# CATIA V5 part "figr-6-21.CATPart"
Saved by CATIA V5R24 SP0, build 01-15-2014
Part number: Part1
Bounding box of the stored display mesh (mm): x 0 to 150, y -70 to 70, z -150 to 69.804
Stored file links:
  D:\KAVITA\CATIA V5-6R2014 Project_ Kavita\CATIA V5-6R2014_partfiles\Partfiles\c06_catia_v5-6r2014_prt\figr-6-21.CATPart
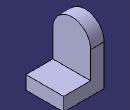
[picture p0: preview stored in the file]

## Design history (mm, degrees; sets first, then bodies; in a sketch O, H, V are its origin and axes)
Body1 (main body)
  Sketch1 on yz-plane, origin (0, 0, 0), H (0, 1, 0), V (0, 0, 1)
    arc A1 centre (0, 0) radius 70 from (70, 0) to (-70, 0) ccw
    point P1 (70, 0)
    point P2 (-70, 0)
    line L1 (-70, 0) -> (-70, -150)
    line L2 (-70, -150) -> (70, -150)
    line L3 (70, -150) -> (70, 0)
    construction circle A2 centre (0, 0) radius 37.5
    radius A1 = 70
    radius A2 = 37.5
    distance O L2 = 150
    coincidence: P1 H, P2 H
    tangency: L1 A1, L3 A1
    horizontal: L2 H
  Pad1: profile Sketch1, direction (1, 0, 0), length 50
  Sketch2 on face of Pad1, origin (50, 0, 0), H (0, 1, 0), V (0, 0, 1)
    line L1 (-70, -150) -> (70, -150)
    line L2 (70, -150) -> (70, -100)
    line L3 (70, -100) -> (-70, -100)
    line L4 (-70, -100) -> (-70, -150)
    reference projected line E1 (-70, -150) -> (70, -150) from edge [face of Pad1 | face of Pad1]
    reference projected line E2 (-70, 0) -> (-70, -150) from edge [face of Pad1 | face of Pad1]
    reference projected line E3 (70, -150) -> (70, 0) from edge [face of Pad1 | face of Pad1]
    length L2 = 50
    horizontal: L1 H, L3 H
    vertical: L2 V, L4 V
    coincidence: L1 E1, E2 L4, L2 E3
  Pad2: profile Sketch2, direction (1, 0, 0), length 100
